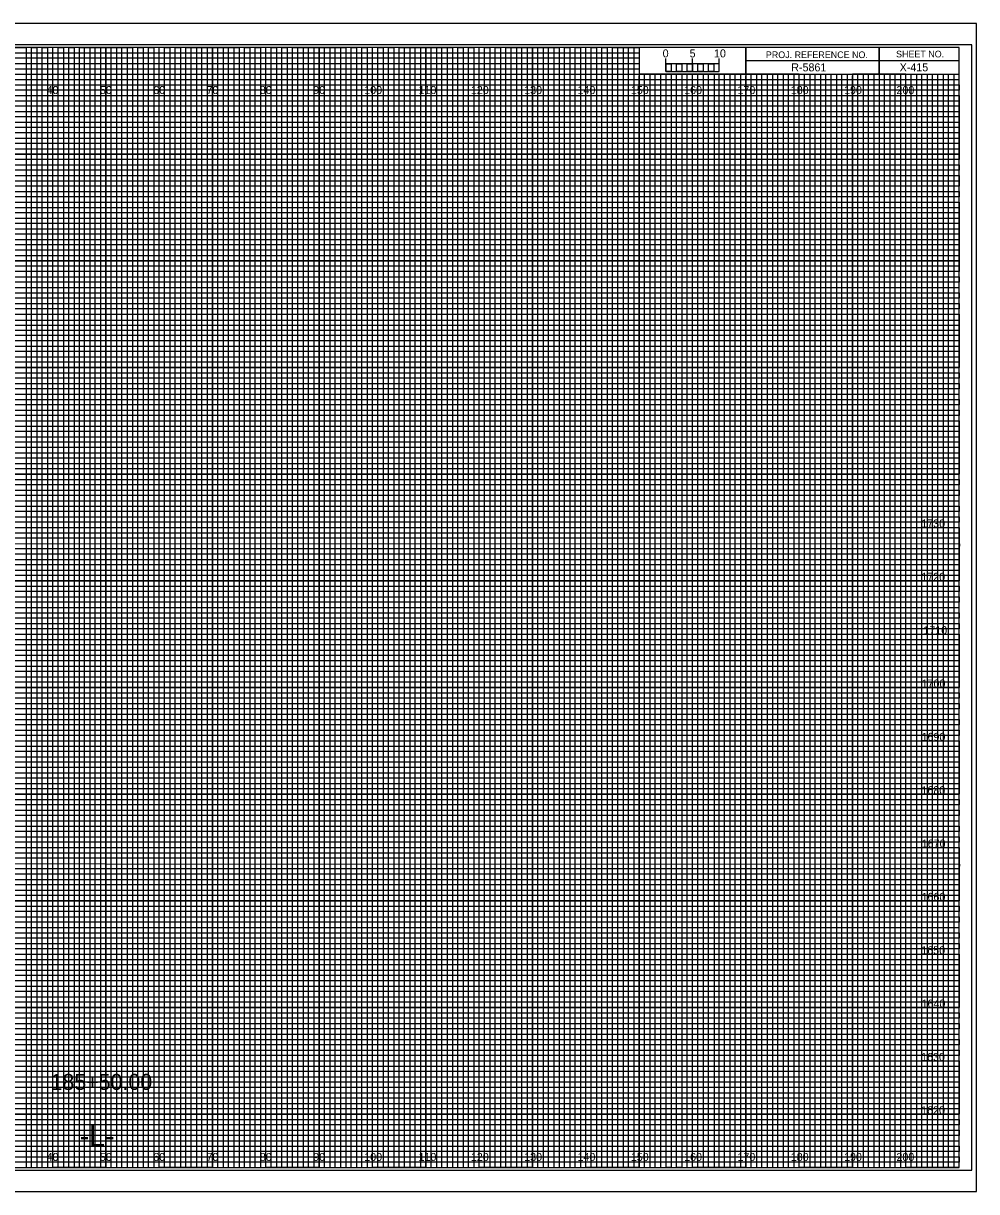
# Model space of a CAD drawing. Extents: x -13 to 323, y -5 to 6154.
# Drawn here: x 144.5 to 323.3, y 2415.5 to 2634.5 of the extents above; entities that cross this region are included whole.
import ezdxf

# ---------------------------------------------------------------- set-up
doc = ezdxf.new("R2010")
doc.units = 0
for name, color, linetype in [('Exist CMT Ground Line', 7, 'Continuous'), ('Prop Horizontal Alignment', 7, 'Continuous'), ('Prop Retaining Wall', 7, 'Continuous'), ('Prop XS Alignment Label', 7, 'Continuous'), ('Prop XS Bar Scale Labels', 7, 'Continuous'), ('Prop XS DDE', 7, 'Continuous'), ('Prop XS DDE Elevations', 7, 'Continuous'), ('Prop XS DDE Slope Text', 7, 'Continuous'), ('Prop XS Earthwork Shape', 7, 'Continuous'), ('Prop XS Elevation Labels', 7, 'Continuous'), ('Prop XS Project Number', 7, 'Continuous'), ('Prop XS Sheet Number', 7, 'Continuous'), ('Prop XS Station Labels', 7, 'Continuous'), ('Raster_Level_0', 7, 'Continuous'), ('Scratch_Level_3', 7, 'Continuous'), ('Sheet Cutting Line CELL', 7, 'Continuous')]:
    doc.layers.add(name, color=color, linetype=linetype)

msp = doc.modelspace()

# ---------------------------------------------------------------- linework, layer by layer
at = {"layer": 'Exist CMT Ground Line'}
for p, q in [((265, 2625.49), (265, 2627.9)), ((265, 2626.9), (265, 2627.9)), ((270, 2625.49), (270, 2627.9)), ((275, 2625.49), (275, 2627.9)), ((275, 2626.9), (275, 2627.9))]:
    msp.add_line(p, q, dxfattribs=at)
for points in [[(275, 2626.9), (265, 2626.9), (265, 2625.49), (275, 2625.49)], [(265, 2626.9), (266, 2626.9), (266, 2625.49), (265, 2625.49)], [(267, 2626.9), (268, 2626.9), (268, 2625.49), (267, 2625.49)], [(269, 2626.9), (270, 2626.9), (270, 2625.49), (269, 2625.49)], [(271, 2626.9), (272, 2626.9), (272, 2625.49), (271, 2625.49)], [(273, 2626.9), (274, 2626.9), (274, 2625.49), (273, 2625.49)]]:
    msp.add_lwpolyline(points, close=True, dxfattribs=at)
at = {"layer": 'Prop Retaining Wall'}
for p, q in [((0, 2629), (260, 2629)), ((260, 2629), (260, 2627.98)), ((260, 2627.98), (0, 2627.98)), ((0, 2627), (260, 2627)), ((260, 2625.89), (0, 2625.89)), ((260, 2627), (260, 2625.89)), ((0, 2624), (320, 2624))]:
    msp.add_line(p, q, dxfattribs=at)
for points in [[(0, 2623), (270, 2623), (320, 2623), (320, 2622), (0, 2622)], [(0, 2621), (320, 2621), (320, 2619), (0, 2619)], [(0, 2618), (320, 2618), (320, 2617), (0, 2616.98)], [(0, 2616), (320, 2616), (320, 2614), (0, 2614)], [(0, 2613), (320, 2613), (320, 2612), (0, 2612)], [(0, 2611), (320, 2611), (320, 2609), (0, 2609)], [(0, 2608), (320, 2608), (320, 2607), (0, 2607)], [(0, 2606), (320, 2606), (320, 2604), (0, 2604)], [(0, 2603), (320, 2603), (320, 2602), (0, 2602)], [(0, 2601), (320, 2601), (320, 2599), (0, 2599)], [(0, 2598), (320, 2598), (320, 2597), (0, 2597)], [(0, 2596), (320, 2596), (320, 2593.95), (320, 2593), (320, 2592), (0, 2592)], [(0, 2594), (320, 2594), (320, 2593), (0, 2593)], [(0, 2591), (320, 2591), (320, 2589), (0, 2589.03)], [(0, 2589.03), (320, 2589), (320, 2588), (0, 2588)], [(0, 2587), (320, 2587), (320, 2586), (0, 2586)], [(0, 2584), (320, 2584), (320, 2583), (0, 2583)], [(0, 2582), (320, 2582), (320, 2581), (0, 2581)], [(-0.07, 2578.89), (320, 2578.89), (320, 2577.88), (-0.07, 2577.88)], [(0, 2577), (320, 2577), (320, 2576), (0, 2576)], [(0, 2574), (320, 2574), (320, 2573), (0, 2573)], [(0, 2572), (320, 2572), (320, 2571), (0, 2571)], [(0, 2569), (320, 2569), (320, 2568), (0, 2568)], [(0, 2567), (320, 2567), (320, 2566), (0, 2566)], [(0, 2564), (320, 2564), (320, 2563), (0, 2563)], [(0, 2562), (320, 2562), (320, 2561), (0, 2561)], [(0, 2559), (320, 2559), (319.99, 2557.98), (0, 2558)], [(0, 2557), (320, 2557), (320, 2556), (0, 2556)], [(0, 2554), (320, 2554), (320, 2553), (0, 2553)], [(0, 2552), (320, 2552), (320, 2551), (0, 2551)], [(0, 2549), (320, 2549), (320, 2548), (0, 2548)], [(0, 2547), (320, 2547), (320, 2546), (0, 2546)], [(0, 2544), (320, 2544), (320, 2543), (0, 2543)], [(0, 2542), (320, 2542), (320, 2541), (0, 2541)], [(0, 2539), (320, 2539), (320, 2538), (0, 2538)], [(0, 2536.99), (320.07, 2536.91), (320, 2536), (0, 2536)], [(0, 2534), (320, 2534), (320, 2533), (0, 2533)], [(0, 2532), (320, 2532), (320, 2531), (0, 2531)], [(0, 2529), (320, 2529), (320, 2528), (0, 2528)], [(0, 2527), (320, 2527), (320, 2526), (0, 2526)], [(0, 2524), (320, 2524), (320, 2523), (0, 2523)], [(0, 2522), (320, 2522), (320, 2521), (0, 2521)], [(0, 2519), (320, 2519), (320, 2518), (0, 2518)], [(0, 2517), (320, 2517), (320, 2516), (0, 2516)], [(0, 2514), (320, 2514), (320, 2513), (0, 2513)], [(0, 2512), (320, 2512), (320, 2511), (0, 2511)], [(0, 2509), (320, 2509), (320, 2508), (0, 2508)], [(0, 2507), (320, 2507), (320, 2506), (0, 2506)], [(0, 2504), (320, 2504), (320, 2503), (0, 2503)], [(0, 2502), (320, 2502), (320, 2501), (0, 2501)], [(0, 2499), (320, 2499), (319.99, 2497.98), (0, 2498)], [(0, 2497), (320, 2497), (320, 2496), (0, 2496)], [(0, 2494), (320, 2494), (320, 2493), (0, 2493)], [(0, 2492), (320, 2492), (320, 2491), (0, 2491)], [(0, 2489), (320, 2489), (320, 2488), (0, 2488)], [(0, 2487), (320, 2487), (320, 2486), (0, 2486)], [(0, 2484), (320, 2484), (320, 2483), (0, 2483)], [(0, 2482), (320, 2482), (320, 2481), (0, 2481)], [(0, 2479), (320, 2479), (320, 2478), (0, 2478)], [(0, 2476.99), (320.07, 2476.91), (320, 2476), (0, 2476)], [(0, 2474), (320, 2474), (320, 2473), (0, 2473)], [(0, 2472), (320, 2472), (320, 2471), (0, 2471)], [(0, 2469), (320, 2469), (320, 2468), (0, 2468)], [(0, 2467), (320, 2467), (320, 2466), (0, 2466)], [(0, 2464), (320, 2464), (320, 2463), (0, 2463)], [(0, 2462), (320, 2462), (320, 2461), (0, 2461)], [(0, 2459), (320, 2459), (320, 2458), (0, 2458)], [(0, 2457), (320, 2457), (320, 2456), (0, 2456)], [(0, 2454), (320, 2454), (320, 2453), (0, 2453)], [(0, 2452), (320, 2452), (320, 2451), (0, 2451)], [(0, 2449), (320, 2449), (320, 2448), (0, 2448)], [(0, 2447), (320, 2447), (320, 2446), (0, 2446)], [(0, 2444), (320, 2444), (320, 2443), (0, 2443)], [(0, 2442), (320, 2442), (320, 2441), (0, 2441)], [(0, 2439), (320, 2439), (320, 2438), (0, 2438)], [(0, 2437), (320, 2437), (320, 2436), (0, 2436)], [(0, 2434), (320, 2434), (320, 2433), (0, 2433)], [(0, 2432), (320, 2432), (320, 2431), (0, 2431)], [(0, 2429), (320, 2429), (320, 2428), (0, 2428)], [(0, 2427), (320, 2427), (320, 2426), (0, 2426)], [(0, 2424), (320, 2424), (320, 2423), (0, 2423)], [(0, 2422), (320, 2422), (320, 2421), (0, 2421)]]:
    msp.add_lwpolyline(points, dxfattribs=at)
at = {"layer": 'Prop XS Alignment Label'}
for p, q in [((305, 2630), (305, 2625)), ((305, 2625), (305, 2630)), ((280, 2627.5), (280, 2625)), ((320, 2627.49), (280, 2627.49)), ((280, 2625), (320, 2625))]:
    msp.add_line(p, q, dxfattribs=at)
for points in [[(320, 2630), (0, 2630), (0, 2420), (320, 2420)], [(280, 2630), (260, 2630), (260, 2625.03), (280, 2625.03)], [(320, 2630), (280, 2630), (280, 2625), (320, 2625)]]:
    msp.add_lwpolyline(points, close=True, dxfattribs=at)
at = {"layer": 'Prop XS DDE'}
msp.add_lwpolyline([(-13.4, 2415.5), (323.3, 2415.5), (323.3, 2634.5), (-13.4, 2634.5)], close=True, dxfattribs=at)
at = {"layer": 'Prop XS DDE Elevations'}
for p, q in [((150, 2420), (150, 2630)), ((160, 2420), (160, 2630)), ((170, 2420), (170, 2630)), ((180, 2420), (180, 2630)), ((190, 2420), (190, 2630)), ((200, 2420), (200, 2630)), ((210, 2420), (210, 2630)), ((220, 2420), (220, 2630)), ((230, 2420), (230, 2630)), ((240, 2420), (240, 2630)), ((250, 2420), (250, 2630)), ((260, 2420), (260, 2624.69)), ((270, 2420), (270, 2624.69)), ((280, 2420), (280, 2624.69)), ((290, 2420), (290, 2624.69)), ((300, 2420), (300, 2624.69)), ((310, 2420), (310, 2624.69)), ((0, 2620), (320, 2620)), ((0, 2610), (320, 2610)), ((0, 2600), (320, 2600)), ((0, 2590), (320, 2590)), ((0, 2580), (320, 2580)), ((0, 2570), (320, 2570)), ((0, 2560), (320, 2560)), ((0, 2550), (320, 2550)), ((0, 2540), (320, 2540)), ((0, 2530), (320, 2530)), ((0, 2520), (320, 2520)), ((0, 2510), (320, 2510)), ((0, 2500), (320, 2500)), ((0, 2490), (320, 2490)), ((0, 2480), (320, 2480)), ((0, 2470), (320, 2470)), ((0, 2460), (320, 2460)), ((0, 2450), (320, 2450)), ((0, 2440), (320, 2440)), ((0, 2430), (320, 2430))]:
    msp.add_line(p, q, dxfattribs=at)
at = {"layer": 'Prop XS DDE Slope Text'}
msp.add_lwpolyline([(-10.8, 2419.5), (322.4, 2419.5), (322.4, 2630.5), (-10.8, 2630.5)], close=True, dxfattribs=at)
at = {"layer": 'Prop XS Earthwork Shape'}
for p, q in [((150, 2630), (140, 2630)), ((150, 2420), (150, 2630)), ((170, 2630), (160, 2630)), ((160, 2630), (160, 2420)), ((170, 2420), (170, 2630)), ((190, 2630), (180, 2630)), ((180, 2630), (180, 2420)), ((190, 2420), (190, 2630)), ((210, 2630), (200, 2630)), ((200, 2630), (200, 2420)), ((210, 2420), (210, 2630)), ((230, 2630), (220, 2630)), ((220, 2630), (220, 2420)), ((230, 2420), (230, 2630)), ((250, 2630), (240, 2630)), ((240, 2630), (240, 2420)), ((250, 2420), (250, 2630)), ((260, 2630), (260, 2420)), ((270, 2420), (270, 2625)), ((290, 2625), (280, 2625)), ((280, 2625), (280, 2420)), ((290, 2420), (290, 2625)), ((310, 2625), (300, 2625)), ((300, 2625), (300, 2420)), ((310, 2420), (310, 2625)), ((160, 2420), (150, 2420)), ((180, 2420), (170, 2420)), ((200, 2420), (190, 2420)), ((220, 2420), (210, 2420)), ((240, 2420), (230, 2420)), ((260, 2420), (250, 2420)), ((280, 2420), (270, 2420)), ((300, 2420), (290, 2420)), ((320, 2420), (310, 2420)), ((320, 2420), (320, 2420))]:
    msp.add_line(p, q, dxfattribs=at)
for points in [[(0, 2620), (320, 2620), (320, 2610), (0, 2610)], [(0, 2600), (320, 2600), (320, 2590), (0, 2590)], [(0, 2580), (320, 2580), (320, 2570), (0, 2570)], [(0, 2560), (320, 2560), (320, 2550), (0, 2550)], [(0, 2540), (320, 2540), (320, 2530), (0, 2530)], [(0, 2520), (320, 2520), (320, 2510), (0, 2510)], [(0, 2500), (320, 2500), (320, 2490), (0, 2490)], [(0, 2480), (320, 2480), (320, 2470), (0, 2470)], [(0, 2460), (320, 2460), (320, 2450), (0, 2450)], [(0, 2440), (320, 2440), (320, 2430), (0, 2430)]]:
    msp.add_lwpolyline(points, dxfattribs=at)
at = {"layer": 'Prop XS Elevation Labels'}
for p, q in [((267, 2625), (266.01, 2625)), ((266.01, 2625), (266.01, 2420)), ((267, 2420), (267, 2625)), ((269, 2625), (268, 2625)), ((268, 2625), (268, 2420)), ((269, 2420), (269, 2625)), ((266.01, 2420), (265, 2420)), ((268, 2420), (267, 2420))]:
    msp.add_line(p, q, dxfattribs=at)
for points in [[(145, 2420), (146, 2420), (146, 2630), (147, 2630), (147, 2420)], [(147, 2420), (148, 2420), (148, 2630), (149, 2630), (149, 2420)], [(150, 2420), (151, 2420), (151, 2630), (152, 2630), (152, 2420)], [(152, 2420), (153, 2420), (153, 2630), (154, 2630), (154, 2420)], [(155, 2420), (156, 2420), (156, 2630), (157, 2630), (157, 2420)], [(157, 2420), (158, 2420), (158, 2630), (159, 2630), (159, 2420)], [(160, 2420), (161, 2420), (161, 2630), (162, 2630), (162, 2420)], [(162, 2420), (163, 2420), (163, 2630), (164, 2630), (164, 2420)], [(165, 2420), (166, 2420), (166, 2630), (167, 2630), (167, 2420)], [(167, 2420), (168, 2420), (168, 2630), (169, 2630), (169, 2420)], [(170, 2420), (171, 2420), (171, 2630), (172, 2630), (172, 2420)], [(172, 2420), (173, 2420), (173, 2630), (174, 2630), (174, 2420)], [(175, 2420), (176, 2420), (176, 2630), (177, 2630), (177, 2420)], [(177, 2420), (178, 2420), (178, 2630), (179, 2630), (179, 2420)], [(180, 2420), (181, 2420), (181, 2630), (182, 2630), (182, 2420)], [(182, 2420), (183, 2420), (183, 2630), (184, 2630), (184, 2420)], [(185, 2420), (186, 2420), (186, 2630), (187, 2630), (187, 2420)], [(187, 2420), (188, 2420), (188, 2630), (189, 2630), (189, 2420)], [(190, 2420), (191, 2420), (191, 2630), (192, 2630), (192, 2420)], [(192, 2420), (193, 2420), (193, 2630), (194, 2630), (194, 2420)], [(195, 2420), (196, 2420), (196, 2630), (197, 2630), (197, 2420)], [(197, 2420), (198, 2420), (198, 2630), (199, 2630), (199, 2420)], [(200, 2420), (201, 2420), (201, 2630), (202, 2630), (202, 2420)], [(202, 2420), (203, 2420), (203, 2630), (204, 2630), (204, 2420)], [(205, 2420), (206, 2420), (206, 2630), (207, 2630), (207, 2420)], [(207, 2420), (208, 2420), (208, 2630), (209, 2630), (209, 2420)], [(210, 2420), (211, 2420), (211, 2630), (212, 2630), (212, 2420)], [(212, 2420), (213, 2420), (213, 2630), (214, 2630), (214, 2420)], [(215, 2420), (216, 2420), (216, 2630), (217, 2630), (217, 2420)], [(217, 2420), (218, 2420), (218, 2630), (219, 2630), (219, 2420)], [(220, 2420), (221, 2420), (221, 2630), (222, 2630), (222, 2420)], [(222, 2420), (223, 2420), (223, 2630), (224, 2630), (224, 2420)], [(225, 2420), (226, 2420), (226, 2630), (227, 2630), (227, 2420)], [(227, 2420), (228, 2420), (228, 2630), (229, 2630), (229, 2420)], [(230, 2420), (231, 2420), (231, 2630), (232, 2630), (232, 2420)], [(232, 2420), (233, 2420), (233, 2630), (234, 2630), (234, 2420)], [(235, 2420), (236, 2420), (236, 2630), (237, 2630), (237, 2420)], [(237, 2420), (238, 2420), (238, 2630), (239, 2630), (239, 2420)], [(240, 2420), (241, 2420), (241, 2630), (242, 2630), (242, 2420)], [(242, 2420), (243, 2420), (243, 2630), (244, 2630), (244, 2420)], [(245, 2420), (246, 2420), (246, 2630), (247, 2630), (247, 2420)], [(247, 2420), (248, 2420), (248, 2630), (249, 2630), (249, 2420)], [(250, 2420), (251, 2420), (251, 2630), (252, 2630), (252, 2420)], [(252, 2420), (253, 2420), (253, 2630), (254, 2630), (254, 2420)], [(255, 2420), (256, 2420), (256, 2630), (257, 2630), (257, 2420)], [(257, 2420), (258, 2420), (258, 2630), (259, 2630), (259, 2420)], [(260, 2420), (261, 2420), (261, 2625), (262.02, 2625), (262.02, 2420)], [(262, 2420), (263, 2420), (263, 2625), (263.99, 2625), (263.99, 2420)], [(270, 2420), (270.98, 2420), (270.98, 2625), (272, 2625), (272, 2420)], [(272, 2420), (273, 2420), (273, 2625), (274.05, 2625), (274.05, 2420)], [(275, 2420), (276, 2420), (276, 2625), (277, 2625), (277, 2420)], [(277, 2420), (278, 2420), (278, 2625), (279, 2625), (279, 2420)], [(280, 2420), (281, 2420), (281, 2625), (282, 2625), (282, 2420)], [(282, 2420), (283, 2420), (283, 2625), (284, 2625), (284, 2420)], [(285, 2420), (286, 2420), (286, 2625), (287, 2625), (287, 2420)], [(287, 2420), (288, 2420), (288, 2625), (289, 2625), (289, 2420)], [(290, 2420), (291, 2420), (291, 2625), (292, 2625), (292, 2420)], [(292, 2420), (293, 2420), (293, 2625), (294, 2625), (294, 2420)], [(295, 2420), (296, 2420), (296, 2625), (297, 2625), (297, 2420)], [(297, 2420), (298, 2420), (298, 2625), (299, 2625), (299, 2420)], [(300, 2420), (301, 2420), (301, 2625), (302, 2625), (302, 2420)], [(302, 2420), (303, 2420), (303, 2625), (304, 2625), (304, 2420)], [(305, 2420), (306, 2420), (306, 2625), (307, 2625), (307, 2420)], [(307, 2420), (308, 2420), (308, 2625), (309, 2625), (309, 2420)], [(310, 2420), (311, 2420), (311, 2625), (312, 2625), (312, 2420)], [(312, 2420), (313, 2420), (313, 2625), (314, 2625), (314, 2420)], [(315, 2420), (316, 2420), (316, 2625), (317, 2625), (317, 2420)], [(317, 2420), (318, 2420), (318, 2625), (319, 2625), (319, 2420)]]:
    msp.add_lwpolyline(points, dxfattribs=at)
at = {"layer": 'Prop XS Station Labels'}
for points in [[(135, 2630), (145, 2630), (145, 2420), (155, 2420), (155, 2630), (165, 2630), (165, 2420), (175, 2420), (175, 2630), (185, 2630), (185, 2420), (195, 2420), (195, 2630), (205, 2630), (205, 2420), (215, 2420), (215, 2630), (225, 2630), (225, 2420), (235, 2420), (235, 2630), (245, 2630), (245, 2420), (255, 2420), (255, 2630), (259.93, 2630), (260, 2630), (260, 2625), (264.99, 2625), (264.99, 2420), (275, 2420), (275, 2625), (285, 2625), (285, 2420), (295, 2420), (295, 2625), (305, 2625), (305, 2420), (315, 2420), (315, 2625)], [(0, 2625), (275, 2625)], [(0, 2605), (320, 2605), (320, 2615), (0, 2615)], [(0, 2585), (320, 2585), (320, 2595), (0, 2595)], [(0, 2565), (320, 2565), (320, 2575), (0, 2575)], [(0, 2545), (320, 2545), (320, 2555), (0, 2555)], [(0, 2525), (320, 2525), (320, 2535), (0, 2535)], [(0, 2505), (320, 2505), (320, 2515), (0, 2515)], [(0, 2485), (320, 2485), (320, 2495), (0, 2495)], [(0, 2465), (320, 2465), (320, 2475), (0, 2475)], [(0, 2445), (320, 2445), (320, 2455), (0, 2455)], [(0, 2425), (320, 2425), (320, 2435), (0, 2435)]]:
    msp.add_lwpolyline(points, dxfattribs=at)
at = {"layer": 'Sheet Cutting Line CELL'}
for p, q in [((323.3, 2634.5), (-13.4, 2634.5)), ((-13.4, 2415.5), (323.3, 2415.5))]:
    msp.add_line(p, q, dxfattribs=at)

# ---------------------------------------------------------------- texts
at = {"layer": 'Exist CMT Ground Line'}
msp.add_text('0', height=1.5, dxfattribs=at).set_placement((264.41, 2628.12))
at = {"layer": 'Prop Horizontal Alignment'}
msp.add_text('185+50.00', height=3, dxfattribs=at).set_placement((149.59, 2434.57))
at = {"layer": 'Prop XS Alignment Label'}
for s, height, p in [('PROJ. REFERENCE NO.', 1.25, (283.77, 2627.99)), ('SHEET NO.', 1.25, (308.19, 2628.12)), ('-L-', 4, (155.06, 2424))]:
    msp.add_text(s, height=height, dxfattribs=at).set_placement(p)
at = {"layer": 'Prop XS Bar Scale Labels'}
for s, p in [('5', (269.47, 2628.12)), ('10', (274.04, 2628.12))]:
    msp.add_text(s, height=1.5, dxfattribs=at).set_placement(p)
at = {"layer": 'Prop XS Project Number'}
msp.add_text('R-5861', height=1.5, dxfattribs=at).set_placement((288.53, 2625.5))
at = {"layer": 'Prop XS Sheet Number'}
msp.add_text('X-415', height=1.5, dxfattribs=at).set_placement((308.86, 2625.51))
at = {"layer": 'Raster_Level_0'}
for s, p in [('40', (148.86, 2621.25)), ('50', (158.86, 2621.25)), ('60', (168.86, 2621.25)), ('70', (178.86, 2621.25)), ('80', (188.86, 2621.25)), ('90', (198.86, 2621.25)), ('100', (208.44, 2621.25)), ('110', (218.62, 2621.25)), ('120', (228.44, 2621.25)), ('130', (238.44, 2621.25)), ('140', (248.44, 2621.25)), ('150', (258.44, 2621.25)), ('160', (268.44, 2621.25)), ('170', (278.44, 2621.25)), ('180', (288.44, 2621.25)), ('190', (298.44, 2621.25)), ('200', (308.26, 2621.25)), ('40', (148.86, 2421.25)), ('50', (158.86, 2421.25)), ('60', (168.86, 2421.25)), ('70', (178.86, 2421.25)), ('80', (188.86, 2421.25)), ('90', (198.86, 2421.25)), ('100', (208.44, 2421.25)), ('110', (218.62, 2421.25)), ('120', (228.44, 2421.25)), ('130', (238.44, 2421.25)), ('140', (248.44, 2421.25)), ('150', (258.44, 2421.25)), ('160', (268.44, 2421.25)), ('170', (278.44, 2421.25)), ('180', (288.44, 2421.25)), ('190', (298.44, 2421.25)), ('200', (308.26, 2421.25))]:
    msp.add_text(s, height=1.5, dxfattribs=at).set_placement(p)
at = {"layer": 'Scratch_Level_3'}
for s, p in [('1730', (312.92, 2540)), ('1720', (312.93, 2530)), ('1710', (313.31, 2520)), ('1700', (312.98, 2510)), ('1690', (312.97, 2500)), ('1680', (312.95, 2490)), ('1670', (313, 2480)), ('1660', (312.97, 2470)), ('1650', (312.92, 2460)), ('1640', (312.97, 2450)), ('1630', (312.89, 2440)), ('1620', (312.9, 2430))]:
    msp.add_text(s, height=1.5, dxfattribs=at).set_placement(p)

doc.saveas('drawing.dxf')
